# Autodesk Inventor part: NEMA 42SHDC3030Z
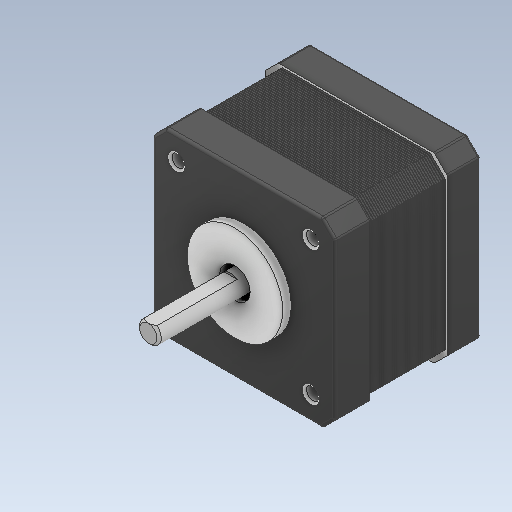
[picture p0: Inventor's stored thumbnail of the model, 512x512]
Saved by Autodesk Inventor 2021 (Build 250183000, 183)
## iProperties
Created: 2012-11
Part Number: NEMA 42SHDC3030Z
Material: Rozsdamentes acél
Document SubType Name: Modeling
Designer: hp
Density: 8.08 g/cm^3
Appearance: Default
Author: hp
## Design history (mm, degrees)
feature "Solid1"
feature "Solid1:1"
feature "Solido2"
body "Solid2"
body "Solid3"
body "Solid4"
